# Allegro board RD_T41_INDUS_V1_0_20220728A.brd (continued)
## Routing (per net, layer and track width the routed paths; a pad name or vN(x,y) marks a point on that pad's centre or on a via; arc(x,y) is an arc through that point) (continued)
DVP_D6: length 47.4
  TOP w0.102: U7.H2 56.05,39.12 56.05,42.1 55.72,42.43 55.72,49.41 60.78,54.47 60.78,60.78 57.88,63.68 53.15,63.68 45.42,71.41 J10.18
DVP_D7: length 45.2
  TOP w0.102: J10.19 45.92,71.44 53.18,64.18 57.72,64.18 61.02,60.88 61.02,54.24 55.95,49.17 55.95,42.52 56.26,42.2 56.26,39.27 56.31,39.22 56.31,38.73 U7.H3
DVP_D8: length 43.5
  TOP w0.102: U7.G1 56.47,39.85 56.47,42.31 56.19,42.59 56.19,49.06 61.27,54.15 61.27,61.03 57.64,64.66 53.16,64.66 46.92,70.9 J10.21
DVP_D9: length 46.7
  TOP w0.102: J10.22 47.42,71.02 53.28,65.16 57.52,65.16 61.51,61.17 61.51,54.02 56.45,48.96 56.45,45.76 56.45,42.64 56.68,42.41 56.68,40.08 56.93,39.83 56.93,39.57 56.63,39.26 U7.G2
DVP_D10: length 44.6
  TOP w0.102: J10.23 47.92,71.02 53.26,65.68 57.44,65.68 61.78,61.34 61.78,53.96 56.68,48.86 56.68,45.85 56.68,42.75 56.91,42.52 56.91,40.23 57.16,39.98 57.16,39.47 56.93,39.24 56.93,38.7 U7.G3
DVP_D11: length 46.4
  TOP w0.102: U7.F2 57.39,39.16 57.39,40.09 57.12,40.36 57.12,42.66 56.91,42.88 56.91,48.77 62.04,53.9 62.04,61.46 57.42,66.08 53.24,66.08 48.42,70.9 J10.24
DVP_HSYNC: length 53.5
  TOP w0.102: TP20.1 40.42,77.17 J10.8 40.42,71.03 50.61,60.85 57.01,60.85 60.24,57.61 60.24,54.83 55.19,49.78 55.19,42.31 55.63,41.88 55.63,39.58 55.33,39.27 U7.J2
DVP_MCLK_PA15: length 22.5
  TOP w0.102: J10.28 50.42,70.5 53.34,67.58 TP10.1 54.98,68.31 57.24,68.31 63.63,61.92 R126.2
DVP_PCLK: length 47.8
  TOP w0.102: J10.26 49.42,70.44 52.97,66.89 55.29,66.89 TP19.1 56.52,66.94 57.38,66.94 62.6,61.71 62.6,53.33 57.17,47.9 57.17,43.09 57.34,42.92 57.34,40.48 57.61,40.2 57.61,38.74 U7.F3
DVP_VSYNC: length 53.8
  TOP w0.102: U7.J3 55.64,38.72 55.64,39.2 55.84,39.4 55.84,41.98 55.42,42.4 55.42,49.6 60.53,54.71 60.53,57.68 57.09,61.12 50.98,61.12 40.92,71.18 J10.9 40.92,77.58 TP22.1
EMMC_3V3: length 6.2
  TOP w0.254: U11.E6 66.57,8.07 v1(66.52,8.12) 66.52,8.12 U11.F5 ; U11.K9 64.99,6.57 v1(64.99,6.57) 64.99,6.1 U11.J10
  BOTTOM w0.381: v1(66.52,8.12) 66.52,8.05 C88.1 65.05,6.57 v1(64.99,6.57) 64.59,6.17 C87.1 64.58,5.85 FB1.2
EMMC_D4: length 5.5
  TOP w0.081: 69.2,9.82 68.77,9.82
  TOP w0.102: 69.2,9.82 69.34,9.97 69.34,13.22 68.55,14.01 R74.2 ; 68.77,9.82 U11.B3
EMMC_D5: length 6.4
  TOP w0.081: 69.42,9.32 68.77,9.32
  TOP w0.102: 68.77,9.32 U11.B4 ; 69.42,9.32 70.11,10.01 70.11,13.65 R75.2
EMMC_D6: length 7.3
  TOP w0.081: 68.84,8.82 69.55,8.82
  TOP w0.102: 68.84,8.82 68.78,8.82 U11.B5 ; R76.2 70.92,13.72 70.92,10.07 69.67,8.82 69.55,8.82
EMMC_D7: length 8.2
  TOP w0.081: U11.B6 68.78,8.32 69.63,8.32
  TOP w0.102: R77.2 71.65,13.87 71.65,10.04 69.93,8.32 69.63,8.32
EMMC_DS: length 1.4
  TOP w0.102: U11.H5 65.52,8.89 v1(65.71,9.08)
  BOTTOM w0.102: TP33.1 65.89,8.9 v1(65.71,9.08)
EMMC_MSC0_CLK: length 17.6
  TOP w0.102: R86.2 v1(63.44,17.73) ; v1(64.01,7.76) 63.84,7.76 U11.M6
  BOTTOM w0.102: v1(63.44,17.73) 63.44,17.79 62.68,18.55 60.76,18.55 60.36,18.16 60.36,17.22 65.09,12.49 C91.1 65.09,8.84 v1(64.01,7.76)
EMMC_MSC0_CMD: length 19.9
  TOP w0.102: v1(63.98,8.39) 63.81,8.57 U11.M5 ; R84.2 v1(64.6,17.79)
  BOTTOM w0.102: v1(64.6,17.79) 63.25,19.14 60.46,19.14 59.64,18.33 59.64,16.36 64.25,11.75 64.25,8.66 v1(63.98,8.39) 63.56,8.39 R78.2
EMMC_MSC0_D0: length 16
  TOP w0.102: U11.A3 69.33,9.57 69.75,9.99 v1(69.75,12.23) ; R131.2 v1(62.29,17.79)
  BOTTOM w0.102: v1(62.29,17.79) 67.85,12.23 v1(69.75,12.23) 70.48,12.23 71.51,11.19 R70.2
EMMC_MSC0_D1: length 16.6
  TOP w0.102: U11.A4 69.56,9.07 70.56,10.07 70.56,11.49 v1(70.53,11.52) ; R133.2 v1(61.14,17.79)
  BOTTOM w0.102: v1(61.14,17.79) 67.23,11.69 70.36,11.69 v1(70.53,11.52) 70.57,11.48 R71.2
EMMC_MSC0_D2: length 16.8
  TOP w0.102: v1(71.3,12.89) 71.3,10.07 69.8,8.57 69.8,8.57 U11.A5 ; R135.2 v1(66.9,17.76)
  BOTTOM w0.102: R72.2 73.26,10.92 v1(71.3,12.89) 71.13,13.05 69.55,13.05 66.9,15.7 v1(66.9,17.76)
EMMC_MSC0_D3: length 14.1
  TOP w0.081: 68.77,10.32 68.77,10.73
  TOP w0.102: 68.77,10.73 v1(68.77,12.75) ; U11.B2 68.77,10.32 ; R137.2 v1(65.75,17.79)
  BOTTOM w0.102: R73.2 70.76,12.62 68.9,12.62 v1(68.77,12.75) 65.75,15.77 v1(65.75,17.79)
EMMC_RST_PB21: length 33.3
  TOP w0.102: v1(63.42,21.59) 63.24,21.77 63.24,24.73 59.22,28.75 U7.C17 ; v1(65.03,7.39) 64.87,7.54 64.87,8.22 U11.K5
  BOTTOM w0.102: v1(65.03,7.39) 64.14,7.39 C92.1 63.34,6.59 62.05,6.59 R79.1 60.85,7.79 60.85,9.13 61.24,9.53 61.24,13.47 59,15.72 59,18.47 60.24,19.71 61.23,19.71 63.11,21.59 v1(63.42,21.59)
EMMC_VDDI: length 3.7
  TOP w0.081: 68.27,10.73 68.27,10.32 68.23,10.27 ; 67.77,10.32 67.77,10.73
  TOP w0.102: 68.27,10.73 68.27,10.84 68.05,11.07 v1(67.96,11.07) 67.77,10.88 67.77,10.73 ; 67.77,10.32 U11.C2 68.23,10.27
  BOTTOM w0.203: C93.1 v1(67.96,11.07)
EXCLKI: length 5.9
  TOP w0.102: C66.2 61.46,43.28 Y1.1 60.92,42.74 R41.2 60.4,41.1 59.78,41.1 59.13,40.45 59.13,39.8 U7.C1
EXCLKO: length 8.1
  TOP w0.102: U7.D2 58.88,39.35 58.88,40.62 R41.1 60.23,41.97 60.23,43.97 Y1.3 59.49,45.72 C67.2
GMAC_MDC: length 18.2
  TOP w0.102: R177.2 42.12,27.54 42.12,21.93 41.06,20.87 38.92,20.87 37.6,19.55 U19.22
GMAC_MDIO: length 19
  TOP w0.102: R178.2 41.72,28.03 41.72,22.13 40.72,21.13 39.43,21.13 R189.2 38.97,21.36 37.65,20.05 U19.23
GMAC_NRST_PB28: length 66.1
  TOP w0.102: v1(68.89,17) 68.52,17 67.63,16.11 67.63,13.24 66.22,11.82 43.11,11.82 v1(42.24,12.69) ; v1(40.64,18.89) R207.2 C151.1 38.7,19.05 U19.21 ; v1(67.93,33.49) 67.81,33.37 66.11,33.37 65.76,33.72 61.21,33.72 60.68,33.2 U7.A11
  L3_PWR w0.102: v1(68.89,17) 68.89,32.78 68.59,33.08 68.33,33.08 v1(67.93,33.49)
  BOTTOM w0.102: v1(42.24,12.69) 42.24,14.51 41.9,14.85 41.9,15.37 41.07,16.2 41.07,18.47 v1(40.64,18.89)
GMAC_PHY_CLK: length 20.2
  TOP w0.102: R175.2 46.68,34.08 45.65,34.08 37.56,25.99 35.59,25.99 33.51,23.91 U19.31
GMAC_RXD0: length 30.9
  TOP w0.102: R195.1 33.04,12.71 36.93,12.71 40.59,16.36 41.47,16.36 44.37,19.26 44.37,25.46 47.4,28.49 48.23,28.49 49.8,30.06 49.8,31.57 U7.U13
GMAC_RXD1: length 32.1
  TOP w0.102: R198.1 33.85,13.69 R193.1 v1(34.41,13.14) 34.51,13.04 36.87,13.04 40.48,16.65 41.21,16.65 44.05,19.48 44.05,25.64 47.18,28.77 48.15,28.77 49.54,30.16 49.54,31.74 50.01,32.21 51.09,32.21 U7.R12
  BOTTOM w0.102: v1(34.41,13.14) 33.87,13.67 R192.2
GMAC_RXDV: length 18.8
  TOP w0.102: U7.U9 49.85,34.22 48.65,34.22 48.09,33.67 46.25,33.67 37.7,25.12 36.54,25.12 35.9,24.47 R191.1
GMAC_TXCLK: length 26.6
  TOP w0.102: R190.1 40.28,17.26 41.27,17.26 43.65,19.63 43.65,26 46.69,29.04 48.1,29.04 49.31,30.26 49.31,31.86 49.89,32.44 50.67,32.44 U7.T12
GMAC_TXD0: length 20
  TOP w0.102: R179.2 46.63,29.59 43.18,26.14 43.18,19.78 41.18,17.78 40.12,17.78 38.3,15.95 36.72,15.95 36.51,16.16 U19.16
GMAC_TXD1: length 19
  TOP w0.102: R180.2 42.87,26.51 42.87,19.94 40.98,18.04 39.86,18.04 38.87,17.05 U19.17
GMAC_TXEN: length 19.3
  TOP w0.102: R176.2 42.51,27.04 42.51,19.99 40.85,18.33 38.46,18.33 38.23,18.55 U19.20
HPOUT: length 55.6
  TOP w0.203: U7.T1 39.44,51.04 31.76,51.04 11.61,71.19 C76.2
I2C0_MIPI_DVP_SCK: length 58.2
  TOP w0.102: J11.20 46.37,60.61 TP29.1 46.37,60.89 v1(46.37,62.2) 46.37,63.87 38.62,71.62 38.61,71.62 38.52,71.71 38.52,71.72 J10.3 ; v1(48,61.92) 49.8,60.11 56.99,60.11 59.69,57.42 59.69,55.04 54.63,49.98 54.63,42.16 55.17,41.62 55.17,39.97 55.02,39.82 55.02,38.05 U7.J4
  BOTTOM w0.102: v1(48,61.92) 46.66,61.92 v1(46.37,62.2)
I2C0_MIPI_DVP_SDA: length 56
  TOP w0.102: 46.88,63.86 39.42,71.32 J10.6 ; 46.88,63.86 50.23,60.52 56.98,60.52 59.95,57.54 59.95,54.93 54.9,49.87 54.9,42.25 55.38,41.77 55.38,39.75 U7.J1 ; 46.88,63.86 TP28.1 46.88,57.94 J11.19
I2C1_SCK_PB26: length 79.4
  TOP w0.102: v1(42.8,41.03) 42.41,40.64 35.01,40.64 33.83,41.82 29.89,41.82 29.34,41.27 24.98,41.27 v1(19.34,35.63) ; U21.6 78.69,37.55 78.24,37.1 74.23,37.1 R152.1 73.3,36.17 73.3,35.08 72.08,33.86 67.2,33.86 v1(67.18,33.89) 67.18,34.25 R184.1
  BOTTOM w0.102: U9.7 16.91,35.57 R46.2 17.74,35.63 v1(19.34,35.63) ; v1(42.8,41.03) 42.8,41.47 46.83,45.5 57.47,45.5 57.95,45.02 61.01,45.02 67.26,38.76 67.26,33.97 v1(67.18,33.89)
I2C1_SDA_PB25: length 85.7
  TOP w0.102: v1(66.5,32.29) 66.78,32.01 R182.1 67.75,31.38 72.01,31.38 74.39,33.77 74.39,36.17 R140.1 79.12,36.72 79.96,37.55 U21.5 ; v1(17.3,33.55) 18.42,33.55 25.91,41.04 29.48,41.04 30,41.56 33.76,41.56 34.93,40.39 42.73,40.39 v1(43.36,41.02)
  BOTTOM w0.102: v1(17.3,33.55) R40.2 16.52,35.07 U9.8 ; v1(43.36,41.02) 43.36,41.68 46.95,45.27 57.34,45.27 57.84,44.77 60.89,44.77 66.82,38.85 66.82,32.61 v1(66.5,32.29)
IRLED_EN_N_PB19: length 99.2
  TOP w0.102: v1(62.32,22.27) 62.32,24.65 58.69,28.28 58.69,29.83 U7.D16
  L3_PWR w0.102: v1(34.11,78.68) 34.11,74.23 v1(43.23,65.1)
  BOTTOM w0.102: Q8.1 28.08,79.86 29,78.94 31.11,78.94 R165.1 32.2,78.69 C102.2 v1(34.11,78.68) ; v1(62.32,22.27) 62.32,22.04 60.76,20.48 49.35,20.48 39.08,30.75 39.08,46.44 38.06,47.45 38.06,55.69 43.48,61.1 43.48,63.4 43.23,63.65 v1(43.23,65.1)
KEY1_PB30: length 45.4
  TOP w0.102: SW1.2 100.01,32.85 93.63,32.85 90.24,29.46 87.54,29.46 R89.1 86.61,28.54 72.11,28.54 69.74,30.9 66.91,30.9 65.6,32.21 59.56,32.21 U7.C12
KEY_IOT_N: length 35.1
  TOP w0.102: SW2.1 100.83,66.44 98.45,64.06 D10.2 96.26,64.06 C95.2 96.18,63.99 R90.2 91.83,60.58 83.15,60.58 73.37,50.8 J9.18
LDR0: length 100.4
  TOP w0.102: v1(60.51,68.01) 60.51,68.03 62.52,70.05 62.52,79.95 68.88,86.31 76.53,86.31 76.98,86.76 76.98,87.92 C125.1 ; R92.1 C125.1 ; C125.1 77.44,89.3 R113.1 ; v1(47.29,25.85) 50.12,28.68 51.32,28.68 51.75,29.1 51.75,30.27 U7.P15
  BOTTOM w0.152: v1(60.51,68.01) 57.14,64.65 53.99,64.65 46.91,57.56 42.39,57.56 39.41,54.59 39.41,48.29 40.44,47.26 40.44,31.75 46.34,25.85 v1(47.29,25.85)
LED_G: length 5.4
  TOP w0.102: v1(69.89,35.39) 69.89,36.32 70.6,37.03 ; v1(69.89,32.67) 69.98,32.58 R181.1
  BOTTOM w0.102: v1(69.89,35.39) v1(69.89,32.67)
LED_R_IOT: length 30.5
  TOP w0.102: R95.1 73.41,41.25 73.41,43.3 80.6,50.49 v1(88.12,50.49) ; v1(88.31,56.85) 88.42,56.97 R225.1
  BOTTOM w0.102: v1(88.31,56.85) 88.04,56.59 88.04,50.57 v1(88.12,50.49)
MCU_PWR: length 100.3
  TOP w0.254: v1(41.64,41.01) 41.62,41 35.1,41 33.89,42.21 24.17,42.21 v1(18.92,36.96) ; v1(86.29,45.93) 81.83,45.93 79.89,43.99 76.54,43.99 v1(76.17,44.36) ; R8.2 v1(89.89,59) ; R90.1 v1(95.24,59.17)
  BOTTOM w0.254: v1(76.17,44.36) 64.25,44.36 62.04,46.57 46.02,46.57 41.64,42.18 v1(41.64,41.01) ; R47.1 v1(18.92,36.96) ; R54.1 88.01,47.83 89.52,47.83 90.85,49.16 90.85,58.04 v1(89.89,59) 95.07,59 v1(95.24,59.17)
  vias: v1(87.25,45.91)
MICBIAS: length 55.7
  TOP w0.254: U7.P3 v1(51.75,38.72)
  TOP w0.305: v1(51.75,41.68) 51.75,42.83 40.96,53.62 38.84,53.62 22.07,70.39 R83.2
  BOTTOM w0.381: v1(51.75,41.68) 51.39,41.32 51.39,40.62 51.75,40.26 v1(51.75,38.72) ; C142.1 51.96,38.93 v1(51.75,38.72) ; v1(51.75,38.72) 51.81,38.66 C141.1
MICNL: length 58.1
  TOP w0.152: C65.2 49.07,43.17 39.89,52.35 38.19,52.35 20.37,70.18 20.37,83.02 R69.1 20.36,83.65 20.36,83.93 C78.1 20.33,84.58 20.33,84.98 D15.2 20.32,85.64 20.32,86.31 19.89,86.74 J7.1
MICPL: length 58
  TOP w0.152: 49.7,43.55 49.19,43.55 40.03,52.71 38.34,52.71 20.72,70.33 20.72,83.02 R80.2 20.72,83.65 20.72,83.93 C78.2 20.69,84.65 20.69,84.91 D9.2 20.68,85.72 20.68,86.3 21.14,86.76 J7.2
MIPI_DVP_IRCUTN_PB18: length 89.4
  TOP w0.102: J11.25 v1(43.87,63.08) ; U7.E17 57.93,27.55 61.04,24.43 61.04,21.59 v1(61.07,21.56) ; J10.31 v1(51.92,71.17)
  BOTTOM w0.102: v1(61.07,21.56) 60.24,20.73 49.46,20.73 39.36,30.83 39.36,46.54 38.32,47.58 38.32,55.54 43.87,61.09 v1(43.87,63.08) 44.06,63.27 44.06,65.41 48.88,70.23 51.3,70.23 51.92,70.85 v1(51.92,71.17)
MIPI_DVP_IRCUTP_PB17: length 96.1
  TOP w0.102: U7.E16 57.93,29.77 58.23,29.47 58.23,27.77 61.45,24.55 v1(61.45,22.3) ; J10.32 v1(52.42,70.67) ; J11.24 44.37,63.83 v1(44.49,63.95)
  BOTTOM w0.102: v1(61.45,22.3) 61.24,22.3 59.94,20.99 49.6,20.99 39.59,31.01 39.59,46.68 38.56,47.71 38.56,55.41 44.19,61.04 44.19,62.73 44.49,63.03 v1(44.49,63.95) 44.49,65.28 49.07,69.86 51.7,69.86 52.42,70.58 v1(52.42,70.67)
MIPI_DVP_MCLK: length 18.9
  TOP w0.102: R126.1 63.63,60.3 R125.1 64.36,58.73 64.36,56.41 63.19,55.24 63.19,52.8 57.63,47.25 TP27.1 57.63,45.33 R38.1
MIPI_DVP_PWDN_PA19: length 24.3
  TOP w0.102: v1(43.59,63.98) 43.37,63.76 43.37,60.75 TP31.1 43.37,60.37 J11.26 ; v1(48.92,71.24) J10.25 ; R143.1 52.47,69.26 v1(51.01,70.72)
  BOTTOM w0.102: v1(51.01,70.72) 49.44,70.72 v1(48.92,71.24) 48.92,70.79 43.59,65.45 v1(43.59,63.98)
MIPI_DVP_RESET: length 62.2
  TOP w0.102: J11.18 47.37,60.55 TP30.1 47.37,60.95 v1(47.37,62.46) ; J10.33 v1(52.92,70.44) 53.66,69.7 57.65,69.7 65.38,61.96 65.38,55.76 64.19,54.58 64.19,51.76 58.53,46.09 58.53,39.52 58.26,39.25 58.26,38.73 U7.E3
  BOTTOM w0.102: v1(52.92,70.44) 52.92,69.56 47.37,64.02 v1(47.37,62.46)
MIPI_MCLK_PA15: length 26.8
  TOP w0.102: R125.2 63.62,58.41 TP32.1 63.62,56.7 v1(63.34,56.41) ; J11.22 v1(45.37,56.35)
  BOTTOM w0.102: v1(63.34,56.41) 63.34,58.69 60.57,61.46 52.08,61.46 47.19,56.57 45.59,56.57 v1(45.37,56.35)
MIPI_RX_2LANE_CLKN0: length 9.6
  TOP w0.104: v1(55.12,56.31) 55.37,56.06 J11.2 ; v1(50.47,53.59) 50.63,53.44 50.63,53.19 R110.2
  BOTTOM w0.104: v1(55.12,56.31) 55.29,56.31 55.45,56.16 55.45,55.19 54.24,53.99 53.67,53.99 53.5,54.16 53.3,54.16 53.13,53.99 52.85,53.99 52.66,54.17 52.47,54.17 52.28,53.99 50.86,53.99 v1(50.47,53.59)
MIPI_RX_2LANE_CLKP0: length 9.6
  TOP w0.104: J11.3 54.87,57.1 v1(55.12,56.85) ; v1(51.08,53.59) 50.89,53.4 50.89,53.19 R108.2
  BOTTOM w0.104: v1(55.12,56.85) 55.7,56.26 55.7,55.09 54.35,53.73 51.22,53.73 v1(51.08,53.59)
MIPI_RX_2LANE_DN0: length 10.4
  TOP w0.104: J11.5 53.87,54.75 53.8,54.68 53.8,54.53 54.04,54.3 56,54.3 56.41,53.88 56.41,53.04 55.68,52.31 54.81,52.31 54.25,52.87 53.92,52.87 R102.2
MIPI_RX_2LANE_DN1: length 8.6
  TOP w0.104: R106.2 48.28,53.21 48.28,53.45 v1(48.13,53.61) ; v1(52.12,56.31) 52.37,56.06 J11.8
  BOTTOM w0.104: v1(52.12,56.31) 52.31,56.13 52.31,55.64 51.8,55.14 49.73,55.14 49.52,54.93 49.35,54.93 49.24,55.04 49.07,55.04 48.95,54.92 48.95,54.74 49.06,54.64 49.06,54.46 48.2,53.61 v1(48.13,53.61)
MIPI_RX_2LANE_DP0: length 10.1
  TOP w0.104: R100.2 53,53.12 54.36,53.12 54.92,52.57 55.58,52.57 56.16,53.15 56.16,53.78 55.89,54.04 55.49,54.04 55.37,53.92 55.37,53.26 55.24,53.14 55.07,53.14 54.95,53.26 54.95,53.92 54.83,54.04 53.93,54.04 53.54,54.43 53.54,54.67 53.37,54.84 J11.6
MIPI_RX_2LANE_DP1: length 8.5
  TOP w0.104: R104.2 48.54,53.2 48.54,53.42 v1(48.74,53.61) ; v1(52.12,56.85) 51.87,57.1 J11.9
  BOTTOM w0.104: v1(48.74,53.61) 48.74,53.78 49.84,54.88 51.91,54.88 52.56,55.53 52.56,56.4 v1(52.12,56.85)
MSC0_CLK: length 16.5
  TOP w0.102: R39.2 55.86,25.51 55.86,22.5 59.1,19.26 63.06,19.26 64.01,18.31 64.01,16.68 R86.1 R85.1
MSC0_CMD: length 20.4
  TOP w0.102: R82.1 R84.1 65.15,16.67 65.15,18.85 64.14,19.85 59.63,19.85 56.71,22.77 56.71,29.22 U7.G17
MSC0_D0: length 20.5
  TOP w0.102: U7.H16 55.98,27.47 55.09,26.58 55.09,22.19 58.63,18.65 62.09,18.65 62.89,17.85 62.89,16.72 R131.1 R87.1
MSC0_D1: length 20.4
  TOP w0.102: R132.1 R133.1 61.72,16.7 61.72,17.87 61.35,18.24 58.67,18.24 54.83,22.09 54.83,26.71 55.63,27.51 55.63,30.3 U7.J15
MSC0_D2: length 22.9
  TOP w0.102: U7.G15 56.94,30.29 56.94,29.85 57.17,29.62 57.17,23.06 59.82,20.41 64.78,20.41 67.49,17.7 67.49,16.7 R135.1 R134.1
MSC0_D3: length 21.6
  TOP w0.102: R136.1 R137.1 66.35,16.71 66.35,18.21 64.43,20.13 59.76,20.13 56.94,22.95 56.94,29.47 56.63,29.78 U7.G16
NTC: length 5.2
  BOTTOM w0.102: TP3.1 17.91,40.01 R11.2 R9.1 17.53,42.84 U1.7
OSC32_XI: length 7.3
  TOP w0.102: Y3.2 52.25,24.89 51.31,25.84 C71.2 51.31,26.92 R52.2 51.46,27.7 51.66,27.89 52.72,27.89 53.38,28.55 U7.M16
OSC32_XO: length 8.3
  TOP w0.102: U7.M15 53.05,30.28 53.05,28.69 52.56,28.19 51.54,28.19 R52.1 50.57,26.92 C72.2 50.57,25.33 Y3.1
OU_PWR_EN_PC18: length 114.6
  TOP w0.102: v1(66.18,60.91) v1(66.18,82.54) ; U7.B5 60.07,37.1 60.39,36.78 60.91,36.78 61.68,37.55 63.4,37.55 v1(74.99,49.14)
  BOTTOM w0.102: v1(74.99,49.14) 74.99,49.27 74.74,49.52 71.53,49.52 68.92,52.13 68.92,58.17 v1(66.18,60.91) ; v1(66.18,82.54) 66.18,82.77 65.01,83.95 40.4,83.95 27.93,71.48 21.2,71.48 19.97,70.25 R233.1 18.44,69.83 D12.2
PHY_LED0: length 22.9
  TOP w0.102: v1(29.93,25.23) 22.01,25.23 R211.2 ; v1(38.39,23.38) R203.1 R202.2 38.45,21.98 38.45,21.56 37.44,20.55 U19.24
  BOTTOM w0.102: v1(29.93,25.23) 35.68,25.23 37.53,23.38 v1(38.39,23.38)
PHY_LED1: length 41.1
  TOP w0.102: R217.2 17.66,5.68 21.37,5.68 23.19,3.86 30.43,3.86 37.68,11.11 v1(37.68,12.2) ; U19.25 36.51,22.7 R206.1 R205.2 v1(37.68,22.52)
  BOTTOM w0.102: v1(37.68,22.52) v1(37.68,12.2)
PIR_3V3: length 51.4
  TOP w0.508: 84.24,70.72 84.24,74.18 ; 84.24,70.72 84.24,70.22 ; 84.24,70.72 84.47,70.49 84.5,70.49 ; 84.24,74.18 84.52,74.46 ; 84.24,74.18 84.24,74.73 ; 84.24,70.22 84.5,70.49 ; 84.24,70.22 84.24,68.62 82.28,66.66 v1(74.78,66.66) ; v1(92.61,72.31) 92.57,72.35 92.57,72.63 90.74,74.46 v1(89.26,74.46) 84.52,74.46 ; 84.5,70.49 v1(86.91,70.49) ; 84.52,74.46 84.5,74.46 84.24,74.73 ; U25.3 92.85,81.63 85.15,81.63 v1(84.58,81.05) 84.24,80.71 v1(84.24,80.64) 84.24,74.73
  BOTTOM w0.254: R265.2 v1(92.61,72.31) ; v1(89.26,74.46) C127.1 88.67,74.46 R227.2 ; D18.1 97.56,75.38 ; U24.4 v1(86.91,70.49) ; R258.2 v1(74.78,66.66)
PIR_H_IOT: length 29.3
  TOP w0.102: v1(92.92,62.61) 92.92,66.27 v1(86.76,72.44)
  BOTTOM w0.102: Q6.1 v1(92.92,62.61) 97.07,58.46 97.07,52.75 96.23,51.91 95.11,51.91 J14.11 ; U24.1 v1(86.76,72.44)
PIR_IOT: length 40.9
  TOP w0.102: R230.1 89.58,48.59 v1(88.97,49.21)
  BOTTOM w0.102: v1(88.97,49.21) 88.15,49.21 87.43,49.94 87.43,64.28 R257.2 88.86,66.96 90.01,68.1 90.01,71.14 91.52,72.65 91.52,79.37 U25.4
PIR_L_IOT: length 28
  TOP w0.102: v1(86.66,68.22) 88.85,68.22 v1(91.03,66.04)
  BOTTOM w0.102: v1(91.03,66.04) Q7.1 93.22,64.77 93.22,63.35 97.87,58.71 97.87,52.1 96.45,50.68 95.16,50.68 J14.13 ; v1(86.66,68.22) 86.35,68.54 U24.7
PIR_PWR_EN_IOT: length 32.5
  TOP w0.102: v1(92.44,71.39) 96.08,71.39 v1(97.77,73.07) ; R220.1 v1(89.89,53.41)
  BOTTOM w0.102: v1(89.89,53.41) 89.17,54.14 89.17,66.47 90.62,67.93 90.62,69.57 v1(92.44,71.39)
  BOTTOM w0.203: U15.3 95.18,72.55 95.7,73.07 v1(97.77,73.07) C126.1 98.61,74.41 D18.2
PLL_AVDD18: length 5.4
  TOP w0.254: U7.D3 v1(58.9,38.72)
  BOTTOM w0.381: v1(58.9,38.72) 58.9,40.43 59.31,40.85 59.78,40.85 C60.1 C59.1 60.03,41.48 FB3.1
POR_CTRL: length 11.5
  TOP w0.102: R122.2 51.89,22.26 53.43,22.26 54,22.84 54,27.17 v1(54.17,27.33) 54.77,27.93 54.77,29.86 U7.K16
  BOTTOM w0.102: v1(54.17,27.33) 54.11,27.27 R121.2
PWR_ON_PC16: length 45.9
  TOP w0.102: J14.2 93.71,59.73 82.83,59.73 71.75,48.65 70.62,48.65 66.95,44.97 66.95,43.28 62.32,38.66 60.78,38.66 U7.A3
PWRON: length 12.8
  TOP w0.102: TP12.1 50.71,22.63 53.35,22.63 53.72,23.01 53.72,27.43 54.52,28.23 54.52,29.52 54.37,29.67 54.37,30.3 U7.K15
RMII_MDCK: length 4.4
  TOP w0.102: U7.R10 51.08,33.5 48.73,33.5 48.33,33.1 48.33,32.71 R177.1
RMII_MDIO: length 3.2
  TOP w0.102: R178.1 48.59,33.85 U7.T10
RMII_PHY_CLK: length 3.3
  TOP w0.102: R175.1 48.19,34.55 49.47,34.55 49.74,34.82 50.27,34.82 50.58,34.5 U7.T9
RMII_TX0: length 5.7
  TOP w0.102: U7.R11 51.1,32.87 50.61,32.87 50.41,32.67 49.8,32.67 48.56,31.42 48.56,30.78 48.31,30.53 48.31,30.02 R179.1
RMII_TX1: length 4.4
  TOP w0.102: U7.T11 50.56,33.2 50.26,32.9 49.69,32.9 48.3,31.5 48.3,30.89 R180.1
RMII_TXEN: length 3
  TOP w0.102: R176.1 47.88,31.44 49.65,33.2 U7.U11
RST_OUT: length 9.9
  TOP w0.102: TP14.1 53.06,21.4 54.27,22.61 54.27,26.84 55.01,27.58 55.01,29.63 U7.J16
RTC_0V8: length 28.9
  TOP w0.254: U13.5 73.84,20.47 C99.1 72.67,21.66 TP34.1 64.31,22.57 v1(64.22,22.65) ; U7.L15 v1(53.7,30.28)
  BOTTOM w0.381: 53.35,26.94 53.01,27.27 53.01,28.76 53.61,29.36 C143.1 53.7,29.56 v1(53.7,30.28)
  BOTTOM w0.508: 53.35,26.94 53.38,26.9 53.38,25.49 55.78,23.09 58.8,23.09 59.55,23.83 63.04,23.83 v1(64.22,22.65)
RTC_1V8: length 39.4
  TOP w0.254: U13.1 75.33,18.34 R142.1
  TOP w0.381: U7.L17 54.03,28.97 v1(54.15,28.84)
  TOP w0.457: C98.1 77.38,15.76 R97.2
  TOP w0.508: v1(71.41,17.73) 72.75,16.4 TP36.1 76.74,16.4 C98.1 76.75,17.56 U13.1
  BOTTOM w0.254: R121.1 54.77,25.8 54.77,25.8
  BOTTOM w0.305: C169.1 54.56,28.43 v1(54.15,28.84)
  BOTTOM w0.508: C169.1 54.77,25.12 56.14,23.75 58.56,23.75 59.33,24.52 63.55,24.52 70.34,17.73 v1(71.41,17.73) C94.1 71.46,16.7 U12.5
RTC_IRQ_N_PB29: length 21.8
  TOP w0.102: U7.B12 59.98,32.44 65.74,32.44 67.03,31.15 72.26,31.15 R153.1 75.39,34.28 77.87,34.28 78.69,33.46 U21.3
RX+: length 17.4
  TOP w0.254: J13.3 7.46,17.39 8.52,18.45 8.52,19.07 8.21,19.39 8.21,20.19 8.81,20.79 11.2,20.79 12.08,19.91 12.08,19.09 15.82,15.34 16.63,15.34 17.66,16.38 U20.14
RX-: length 17.5
  TOP w0.254: U20.16 17.59,13.84 16.63,14.8 15.6,14.8 14.63,15.77 14.21,15.77 13.47,15.03 13.05,15.03 12.75,15.33 12.75,15.75 13.49,16.49 13.49,16.91 13.2,17.21 12.78,17.21 12.03,16.47 11.61,16.47 11.31,16.77 11.31,17.19 12.06,17.93 12.06,18.35 11.54,18.86 11.54,19.69 10.98,20.25 9.71,20.25 J13.6
RX_N1: length 7.8
  TOP w0.104: U19.6 31.81,18.05 31.69,18.17 30.99,18.17 30.04,17.22 30.04,15.51 29.43,14.9 28.92,14.9 27.86,13.84 U20.1
RX_P1: length 7.8
  TOP w0.104: U19.5 31.81,18.55 31.69,18.43 30.88,18.43 29.78,17.33 29.78,15.62 29.32,15.16 29.06,15.16 27.84,16.38 U20.3
RXDV: length 2.5
  TOP w0.102: v1(31.67,16.65) 32.07,17.05 U19.8
  BOTTOM w0.102: v1(31.67,16.65) 31.67,16.06 R196.2 30.89,15.92 R197.1
SD0_CD_N_PB27: length 62.1
  TOP w0.102: J6.9 v1(41.87,13.51) 41.87,12.52 42.81,11.58 66.32,11.58 67.89,13.15 67.89,16 68.5,16.61 69.08,16.61 v1(69.49,17.02) ; v1(68.47,33.47) 68.13,33.13 66.01,33.13 65.66,33.48 61.29,33.48 60.7,32.9 60.4,32.9 60.1,33.2 U7.B11
  L3_PWR w0.102: v1(69.49,17.02) 69.13,17.38 69.13,32.92 68.58,33.47 v1(68.47,33.47)
  BOTTOM w0.102: v1(41.87,13.51) 41.87,14.42 R88.1
SD0_MSC0_CLK: length 22
  TOP w0.102: R85.2 63.44,13.74 63.06,13.35 59.88,13.35 55.22,18.01 47.76,18.01 46.28,16.53 J6.5
SD0_MSC0_CMD: length 21.4
  TOP w0.102: J6.3 v1(48.47,16.32) 49.42,17.26 54.9,17.26 59.3,12.86 63.87,12.86 64.6,13.58 R82.2
  BOTTOM w0.102: v1(48.47,16.32) 48.48,16.31 R61.2
SD0_MSC0_D0: length 23.4
  TOP w0.102: J6.7 v1(44.07,16.32) 46.39,18.63 55.71,18.63 60.46,13.88 61.87,13.88 R87.2
  BOTTOM w0.102: v1(44.07,16.32) 44.06,16.3 R62.2
SD0_MSC0_D1: length 23.3
  TOP w0.102: J6.8 v1(42.97,16.32) 45.69,19.03 55.83,19.03 60.56,14.31 R132.2
  BOTTOM w0.102: R63.2 42.97,16.31 v1(42.97,16.32)
SD0_MSC0_D2: length 21.3
  TOP w0.102: R134.2 66.9,13.58 65.63,12.3 58.88,12.3 54.69,16.49 50.85,16.49 v1(50.67,16.32) J6.1
  BOTTOM w0.102: v1(50.67,16.32) 50.66,16.3 R64.2
SD0_MSC0_D3: length 21.4
  TOP w0.102: J6.2 v1(49.57,16.32) 50.1,16.84 54.83,16.84 59.11,12.57 64.79,12.57 65.75,13.53 R136.2
  BOTTOM w0.102: v1(49.57,16.32) 49.57,16.31 R65.2
SD_PWR_EN_N_PB20: length 39.1
  TOP w0.102: v1(62.36,21.56) 61.94,21.98 61.94,24.58 58.46,28.06 58.46,29.62 58.23,29.85 58.23,30.29 U7.E15
  BOTTOM w0.102: v1(62.36,21.56) 60.99,20.2 58.77,20.2 56.72,18.15 56.72,11.79 54.79,9.86 49.37,9.86 Q3.1 46.42,10.53 R66.2 44.83,10.54 C82.2
SENS1: length 15.6
  BOTTOM w0.305: U25.2 93.65,76.36 C204.1 R267.2 R265.1 93.65,69.04 92.55,67.94 Q7.2 91.57,67.94 90.31,66.68 90.31,65.34 91.15,64.51 Q6.2
SFC1_CS_N: length 23.5
  TOP w0.102: v1(36.82,34.93) 36.82,35.02 37.81,36.01 48.52,36.01 48.85,36.33 50.43,36.33 50.64,36.12 51.11,36.12 U7.R7
  BOTTOM w0.102: U18.1 33.64,36.56 R123.1 32.26,35.06 36.68,35.06 v1(36.82,34.93)
SFC1_SCLK: length 17.9
  TOP w0.102: v1(36.61,33.13) 39.37,33.13 41.34,35.09 49.3,35.09 49.45,35.24 50.68,35.24 U7.T8
  BOTTOM w0.102: U18.6 36.18,32.7 v1(36.61,33.13)
SFC1_SIO0: length 18.1
  TOP w0.102: U7.R8 51.09,35.49 49.38,35.49 49.22,35.32 40.39,35.32 38.84,33.78 v1(37.45,33.78)
  BOTTOM w0.102: U18.5 v1(37.45,33.78)
SFC1_SIO1: length 18.4
  TOP w0.102: v1(37.61,35.24) 38.14,35.78 48.95,35.78 49.27,36.1 50.3,36.1 50.6,35.8 U7.T7
  BOTTOM w0.102: v1(37.61,35.24) 37.22,35.63 35.46,35.63 34.91,36.18 U18.2
SFC1_SIO2: length 15.6
  TOP w0.102: v1(38.38,35.41) 38.52,35.55 49.09,35.55 49.34,35.8 U7.U7
  BOTTOM w0.102: U18.3 36.18,37.05 36.79,36.44 37.35,36.44 v1(38.38,35.41)
SFC1_SIO3: length 19.4
  TOP w0.102: v1(35.33,32.37) 39.85,32.37 42.3,34.82 49.39,34.82 49.6,35.03 50.43,35.03 50.63,34.83 51.1,34.83 U7.R9
  BOTTOM w0.102: v1(35.33,32.37) 34.91,31.95 U18.7
SFC_CS_N: length 20.1
  TOP w0.102: U8.1 33.58,37.84 33.58,39.02 33.34,39.27 R44.1 33.79,39.64 35.46,37.97 50.56,37.97 U7.T4
SFC_SCLK: length 19.3
  TOP w0.102: U8.6 31.03,32.05 32.4,33.42 33.69,33.42 36.8,36.54 46.68,36.54 R43.1
SFC_SIO0: length 24.4
  TOP w0.102: U7.U5 49.94,37.28 36.61,37.28 33.5,34.18 31.5,34.18 29.76,32.45 U8.5
SFC_SIO1: length 22.1
  TOP w0.102: U7.R5 51.11,37.42 50.59,37.42 50.26,37.74 36.1,37.74 33.97,35.61 33.06,35.61 32.3,36.36 U8.2
SFC_SIO2: length 23.4
  TOP w0.102: U8.3 31.03,35.62 31.67,34.98 33.82,34.98 36.35,37.51 50.16,37.51 50.57,37.1 U7.T5
SFC_SIO3: length 21.8
  TOP w0.102: U7.T6 50.67,36.56 48.51,36.56 48.2,36.24 37.62,36.24 33.91,32.54 33.05,32.54 32.3,31.79 U8.7
SLCD_BLEN: length 41.7
  TOP w0.102: v1(89.32,35.76) 89.02,35.76 83.19,41.59 77,41.59 R183.1
  BOTTOM w0.102: R212.1 98.79,26.56 U23.16 ; R212.1 98.29,26.21 U23.15 ; R212.1 97.54,27.8 95.75,27.8 89.32,34.24 v1(89.32,35.76)
SLCD_BT656_D0: length 36.1
  TOP w0.102: R130.1 90.54,19.85 R144.1 90.05,20.33 82.78,20.33 82.36,20.75 82.36,22.27 78.12,26.51 65.28,26.51 61.19,30.6 U7.A15
SLCD_BT656_D1: length 37.2
  TOP w0.102: R145.1 90.54,18.71 R146.1 90.05,19.19 87.62,19.19 86.78,20.03 82.61,20.03 82.14,20.51 82.14,22.07 78.73,25.48 65.83,25.48 61.03,30.28 60.39,30.28 60.07,30.6 U7.B15
SLCD_BT656_D2: length 37.7
  TOP w0.102: U7.A16 60.9,29.95 65.67,25.19 78.53,25.19 81.84,21.88 81.84,18.84 82.63,18.05 90.05,18.05 R150.1 90.54,17.57 R149.1
SLCD_BT656_D3: length 40
  TOP w0.102: R154.1 90.54,16.42 R155.1 90,16.96 87.84,16.96 87.08,17.72 82.42,17.72 81.45,18.68 81.45,21.88 78.39,24.94 65.43,24.94 60.75,29.62 60.39,29.62 60.19,29.82 60.19,30.15 60.07,30.27 59.56,30.27 U7.C15
SLCD_BT656_D4: length 39.7
  TOP w0.102: U7.A17 60.53,29.3 65.69,24.14 78.84,24.14 81.13,21.84 81.13,16.91 82.52,15.52 88.14,15.52 88.45,15.84 89.98,15.84 R158.1 90.54,15.28 R156.1
SLCD_BT656_D5: length 41.1
  TOP w0.102: U7.B16 59.88,29.78 60.19,29.47 60.19,29.19 65.48,23.9 78.51,23.9 80.84,21.57 80.84,16.64 82.28,15.2 87.59,15.2 88.07,14.72 89.95,14.72 R161.1 90.54,14.14 R160.1
SLCD_BT656_D6: length 42.5
  TOP w0.102: R162.1 90.54,12.99 R163.1 89.92,13.6 88.57,13.6 87.78,12.82 83.04,12.82 80.5,15.36 80.5,21.36 78.23,23.63 65.21,23.63 59.88,28.97 U7.B17
SLCD_BT656_D7: length 43.5
  TOP w0.102: R164.1 90.54,11.85 R166.1 89.98,12.4 82.98,12.4 80.21,15.17 80.21,21.24 78.05,23.4 65.12,23.4 59.56,28.96 59.56,29.62 U7.C16
SLCD_CS: length 34.6
  TOP w0.102: U7.B13 60.07,31.9 60.37,31.6 62.02,31.6 66.16,27.46 78.97,27.46 80.84,25.58 86.99,25.58 88.28,24.3 R171.1
SLCD_CS_PD10: length 4.4
  TOP w0.102: R171.2 93.65,25.63 J15.7
SLCD_D0_PD00: length 4.8
  TOP w0.102: R130.2 94.54,17.63 J15.23
SLCD_D1_PD01: length 4.5
  TOP w0.102: R145.2 93.9,17.13 J15.24
SLCD_D2_PD02: length 4.3
  TOP w0.102: J15.25 93.33,16.63 92.39,17.57 R149.2
SLCD_D3_PD03: length 4
  TOP w0.102: R154.2 92.62,16.13 J15.26
SLCD_D4_PD04: length 4
  TOP w0.102: J15.27 92.66,15.63 R156.2
SLCD_D5_PD05: length 4.3
  TOP w0.102: J15.28 93.31,15.13 R160.2
SLCD_D6_PD06: length 4.6
  TOP w0.102: J15.29 93.95,14.63 R162.2
SLCD_D7_PD07: length 4.8
  TOP w0.102: J15.30 94.59,14.13 R164.2
SLCD_DC: length 35.6
  TOP w0.102: R172.1 88.71,23.41 86.8,25.32 80.67,25.32 78.76,27.22 65.96,27.22 61.82,31.37 60.24,31.37 60.01,31.6 59.53,31.6 U7.C13
SLCD_DC_PD11: length 4.6
  TOP w0.102: J15.8 94.04,25.13 R172.2
SLCD_IOVDD: length 7.3
  TOP w0.292: 94.89,13.13 J15.32
  TOP w0.381: R147.2 91.99,10.1 C105.1 C106.1 93.79,10.68 93.79,12.03 94.89,13.13
SLCD_LEDA: length 4.6
  TOP w0.279: J15.16 v1(94.78,21.13)
  BOTTOM w0.254: 97.05,21.9 97.29,22.14 U23.8
  BOTTOM w0.381: 97.05,21.9 C185.2 96.27,21.13 v1(94.78,21.13)
SLCD_LEDK: length 8
  TOP w0.279: J15.18 v1(97.63,20.13) ; J15.20 v1(97.62,19.13) ; J15.19 97.56,19.63 ; J15.17 97.69,20.63
  BOTTOM w0.229: U23.4 100.25,23.13
  BOTTOM w0.254: U23.6 98.29,21.72 ; 98.79,21.57 U23.5
SLCD_RDY: length 36
  TOP w0.102: R174.1 87.49,21.63 86.43,22.68 82.39,22.68 78.33,26.74 65.53,26.74 61.36,30.91 59.57,30.91 U7.C14
SLCD_RDY_PD12: length 5.8
  TOP w0.102: R157.1 R174.2 94.81,24.13 J15.10
SLCD_RST_PD09: length 18.7
  TOP w0.102: v1(92.98,25.64) 92.52,25.19 R170.2 ; v1(93.02,12) 94.65,13.63 J15.31
  BOTTOM w0.102: v1(92.98,25.64) 92.51,25.17 92.51,12.51 v1(93.02,12)
SLCD_TE: length 33.5
  TOP w0.102: R170.1 89.2,25.19 86.66,27.72 66.35,27.72 62.18,31.9 U7.A13
SLCD_VCI: length 7.7
  TOP w0.292: J15.33 95.14,12.63
  TOP w0.381: 95.14,12.63 94.36,11.85 94.36,10.27 93.26,9.16 C179.1 93.07,9.16 C180.1 91.35,9.16 R148.2
SLCD_WR_BT656_PCLK: length 35
  TOP w0.102: R168.1 91.27,22.52 R169.1 90.02,23.03 82.52,23.03 78.56,26.98 65.75,26.98 61.59,31.14 59.99,31.14 U7.B14
SLCD_WR_PD08: length 4.8
  TOP w0.102: J15.9 94.42,24.63 R168.2
SOC_0V8: length 10.2
  TOP w0.203: U7.N9 v1(52.4,34.83) U7.N8 ; U7.N10 v1(52.4,33.53) ; U7.N6 v1(52.4,36.13) U7.N7
  TOP w0.254: U7.J13 v1(55,32.22) 54.68,31.9 U7.K13 ; U7.L5 v1(54.35,37.43) U7.K5 ; U7.H7 v1(56.3,36.13) U7.H6 ; U7.H12 v1(56.3,32.22) U7.H13 ; U7.M6 v1(53.05,36.78) U7.M5 ; U7.H10 v1(56.3,33.53) U7.H11 ; U7.J5 v1(55.65,37.43) U7.H5 ; U7.H9 v1(56.3,34.83) U7.H8
  BOTTOM w0.381: FB4.1 48.97,35.44
  vias: v1(55.67,31.55) v1(56.2,31.15) v1(57.78,25.58) v1(57.78,24.97) v1(57.79,24.38) v1(58.33,25.59) v1(58.36,24.96) v1(58.36,24.36)
SOC_1V8: length 57.9
  TOP w0.203: U7.N11 v1(52.4,32.87)
  TOP w0.254: U7.K2 v1(54.35,38.72)
  BOTTOM w0.381: 55.41,43.86 55.74,44.19 ; 55.41,43.86 55.41,44.19 55.4,44.19 ; 55.41,43.86 55.41,43.85 ; 54.21,43.78 53.8,44.19 ; 54.21,43.78 54.21,43.81 ; 54.21,43.78 C174.1 C175.1 54.21,39.72 54.35,39.58 v1(54.35,38.72) ; 54.2,44.19 54.21,44.18 54.21,43.81 ; R185.1 64.65,38.41 FB2.2 ; FB7.1 49.89,30.41 49.89,31.88 C176.1 C177.1 51.61,32.48 52.01,32.87 v1(52.4,32.87) ; 54.21,43.81 54.6,44.19 ; 55.41,43.85 FB10.2 ; 55.41,43.85 55.06,44.19
  BOTTOM w0.508: R185.1 63.84,40.25 61.75,42.34 FB3.2 61.13,42.52 60.61,43.04 57.91,43.04 56.76,44.19 51.87,44.19 ; FB7.1 48.39,29.34 43.81,33.92 43.81,36.78 FB5.1 45.07,38.18 44.57,38.69 44.57,40.78 45.47,41.68 v1(45.51,41.68) 45.51,41.92 47.78,44.19 51.21,44.19
  vias: v1(34.91,42.9) v1(35.15,42.48) v1(44.93,41.71)
SOC_3V3: length 134.3
  TOP w0.203: U7.P9 v1(51.75,34.18)
  TOP w0.254: v1(80.04,9.03) 80.34,9.34 R45.2 ; v1(55.04,30.96) U7.J14 ; v1(20.74,35.19) 26.2,40.65 29.68,40.65 30.22,41.2 33.67,41.2 35.15,39.72 v1(37.9,39.72)
  TOP w0.305: R42.2 v1(77.39,9.51)
  TOP w0.381: v1(77.39,9.51) 75.96,8.08 75.96,6.96 76.38,6.54 J4.1 ; v1(64.06,37.65) 64.12,37.65 v1(65.27,38.8)
  TOP w0.508: v1(44.6,34.09) 44.6,34.06 v1(43.67,33.14)
  BOTTOM w0.254: v1(20.74,35.19) R46.1 R40.1 ; v1(77.39,9.51) 77.86,9.03 v1(80.04,9.03)
  BOTTOM w0.381: v1(51.75,34.18) 51.75,34.06 51.73,34.03 51.73,33.49 51.42,33.18 50.06,33.18 49.37,32.49 C171.1 ; R138.1 63.84,37.87 v1(64.06,37.65) ; v1(45.17,40.5) 45.17,39.12 FB6.1 ; 52.24,26.99 52.48,27.24 52.48,29 52.93,29.45 52.93,30.22 53.67,30.96 v1(55.04,30.96)
  BOTTOM w0.508: C171.1 49.25,32.48 C170.1 46.21,32.48 v1(44.6,34.09) ; v1(65.27,38.8) 64.52,39.55 64.52,40.52 60.72,44.33 57.6,44.33 57.09,44.84 47.22,44.84 43.92,41.53 v1(43.92,40.58) ; v1(42.18,39.62) 42.18,34.63 v1(43.67,33.14) 49.89,26.93 52.18,26.93 52.24,26.99 52.24,25.68 55.47,22.44 59.31,22.44 60.06,23.2 62.62,23.2 67.9,17.91 67.9,16.12 70.16,13.86 73.03,13.86 v1(77.39,9.51)
  vias: v1(38.47,39.7)
SOC_BT_RST_N/PIR_IOT: length 5.5
  TOP w0.102: J14.16 95.18,48.17 92.08,48.17 R230.2 91.65,47.66 R229.2
SOC_BT_RST_PC17: length 37.1
  TOP w0.102: R229.1 81.53,47.65 78.67,44.79 76.24,44.79 v1(75.91,45.11) ; v1(68.85,46.35) 67.41,44.9 67.41,43.28 62.51,38.39 61.05,38.39 60.71,38.05 60.22,38.05 U7.B3
  BOTTOM w0.102: v1(75.91,45.11) 74.62,46.4 68.91,46.4 v1(68.85,46.35)
SOC_PWR_EN_IOT: length 89.3
  TOP w0.102: v1(67.02,61.25) v1(67.02,83.03)
  BOTTOM w0.102: J9.17 69.68,52.65 69.68,58.6 v1(67.02,61.25) ; D12.1 27.83,71.73 40.3,84.2 65.22,84.2 66.38,83.03 v1(67.02,83.03)
SOC_WIFI_OOB_PC15: length 45.2
  TOP w0.102: J14.1 92.73,59.44 83.08,59.44 71.9,48.26 71.47,48.26 67.82,44.6 67.82,43.08 62.78,38.05 61.35,38.05 61.05,37.75 U7.B4
SPEAK_EN: length 109
  TOP w0.102: v1(76.52,46.96) 72.96,43.4 72.96,42.49 68.76,38.29 68.76,37.47 65.57,34.28 61.04,34.28 60.72,33.96 59.98,33.96 U7.B10 ; v1(41.24,47.83) 31.89,47.83 27.72,52 27.72,53.68 9.97,71.43 9.97,76.92 R58.1 9.49,77.49 U10.1
  BOTTOM w0.102: v1(76.52,46.96) 76.25,47.23 64.47,47.23 63.43,48.27 41.68,48.27 v1(41.24,47.83)
TEST_TE: length 1.8
  TOP w0.102: U7.L13 v1(53.7,31.57)
  BOTTOM w0.102: v1(53.7,31.57) 53.1,31.57 TP16.1
TRST_: length 4.1
  TOP w0.102: v1(57.57,30.99) 58.31,30.99 U7.D14
  BOTTOM w0.102: v1(57.57,30.99) 57.57,28.37 TP15.1
TX+: length 22.8
  TOP w0.254: J13.1 6.99,15.16 6.32,15.16 5.28,16.2 5.28,21.22 7.52,23.46 11.52,23.46 13.2,21.77 16.71,21.77 17.66,22.73 U20.9
TX-: length 22.9
  TOP w0.254: U20.11 17.74,20.19 16.68,21.24 15.17,21.24 14.87,20.94 14.15,20.94 13.86,21.24 12.98,21.24 11.3,22.92 7.74,22.92 5.81,20.99 5.81,16.42 6.54,15.69 9.22,15.69 J13.2
TX_N0: length 6.8
  TOP w0.104: U20.6 27.94,20.19 29.06,21.31 29.54,21.31 29.98,20.87 30.35,20.5 30.35,19.68 30.86,19.17 31.69,19.17 31.81,19.05 U19.4
TX_P0: length 6.8
  TOP w0.104: U20.8 27.9,22.73 29.06,21.57 29.65,21.57 30.61,20.61 30.61,19.79 30.97,19.43 31.69,19.43 31.81,19.55 U19.3
UART1_RXD: length 34.2
  TOP w0.102: U7.F16 57.4,29.83 57.4,27.25 60.42,24.22 60.42,21.38 60.89,20.91 66.75,20.91 74.82,12.84 77.28,12.84 78.43,11.69 R42.1 78.42,10.21 R48.2
UART1_TXD: length 35.3
  TOP w0.102: U7.F15 57.62,30.25 57.62,27.34 60.65,24.32 60.65,21.48 60.99,21.13 66.87,21.13 74.85,13.15 77.29,13.15 78.98,11.47 78.98,10.54 R45.1 79.31,10.21 R51.2
UART2_RXD_PC14: length 39.4
  TOP w0.102: R215.1 89.04,51.64 v1(89.02,51.62) ; v1(89.02,50.48) 88.65,50.85 79.66,50.85 64.08,35.27 60.31,35.27 60.09,35.49 59.54,35.49 U7.C7
  BOTTOM w0.102: v1(89.02,50.48) v1(89.02,51.62)
UART2_TXD_PC13: length 42.9
  TOP w0.102: U7.B7 60.1,35.8 60.4,35.5 63.93,35.5 79.52,51.09 92.15,51.09 92.57,50.67 95.14,50.67 J14.12
USB_AVD08: length 3.4
  TOP w0.254: U7.R4 v1(51.1,38.07)
  BOTTOM w0.381: v1(51.1,38.07) 50.33,38.07 C136.1 C135.1 50.06,36.87 FB4.2
USB_AVD18: length 4.8
  TOP w0.254: U7.T3 v1(50.45,38.72)
  BOTTOM w0.381: FB5.2 46.32,38.19 C137.1 47.16,38.19 C138.1 48.25,38.19 48.78,38.72 v1(50.45,38.72)
USB_AVD33: length 5.6
  TOP w0.254: U7.R3 v1(51.1,38.72)
  BOTTOM w0.305: v1(51.1,38.72) 50.47,39.36 50.14,39.36
  BOTTOM w0.381: FB6.2 47.14,39.07 C139.1 C140.1 48.35,39.36 50.14,39.36
USB_DET_IOT: length 3.2
  TOP w0.102: R188.1 89.16,55.19 C9.1 88.27,55.19 R12.2 R10.1
USB_DM0: length 48.9
  TOP w0.13: U7.U1 50.1,39.68 49.32,39.68 41.81,47.19 8.17,47.19 D2.2 7.15,47.18 5.52,47.18 5.35,47.35 J2.2
USB_DP0: length 49.7
  TOP w0.13: U7.T2 50.45,39.37 49.2,39.37 41.69,46.88 8.17,46.88 D1.2 7.16,46.87 5.53,46.87 5.36,46.7 J2.3
USB_ID: length 2.6
  TOP w0.102: R55.1 48.22,39.05 U7.U2
USB_VBUS: length 5.3
  TOP w0.254: U7.U3 46.13,38.4 R24.1 45.85,39.57 R27.1
VCM: length 2.8
  TOP w0.254: U7.R2 v1(51.1,39.37)
  BOTTOM w0.305: v1(51.1,39.37) 51.06,39.37 50.18,40.26 C68.1 C69.1
VOUT: length 8
  BOTTOM w0.254: U16.2 73.1,71.87 R259.2 74.72,71.14 C198.1 75.59,71.14 R255.1
WIFI_MSC1_CLK_PC02: length 25
  TOP w0.102: U7.A1 60.7,39.87 62.39,39.87 65.85,43.34 65.85,53.7 67.42,55.27 72.18,55.27 J9.10
WIFI_MSC1_CMD_PC03: length 26.7
  TOP w0.102: J9.7 69.72,57.15 R246.2 68.51,55.94 67.46,55.94 65.41,53.88 65.41,43.25 62.26,40.1 60.44,40.1 60.19,39.86 60.19,39.58 59.97,39.36 59.75,39.36 59.57,39.18 59.57,38.74 U7.C3
WIFI_MSC1_D0_PC04: length 23.9
  TOP w0.102: J9.11 69.08,54.61 R247.2 68.61,54.19 67.18,54.19 66.27,53.29 66.27,43.37 62.51,39.61 60.88,39.61 60.65,39.37 60.36,39.37 60.04,39.05 U7.B2
WIFI_MSC1_D1_PC05: length 24
  TOP w0.102: U7.A2 60.66,39.05 60.99,39.38 62.64,39.38 66.56,43.3 66.56,52.35 67.51,53.3 68.61,53.3 R248.2 69.29,53.98 72.16,53.98 J9.14
WIFI_MSC1_D2_PC06: length 27.6
  TOP w0.102: J9.5 71.49,58.45 R249.2 68.59,57.99 67.34,57.99 66.67,57.32 66.67,56.18 64.76,54.27 64.76,43.38 61.96,40.58 60.32,40.58 59.53,39.8 59.53,39.54 59.22,39.24 U7.C2
WIFI_MSC1_D3_PC07: length 27.5
  TOP w0.102: U7.B1 59.88,39.84 60.37,40.33 62.17,40.33 65.12,43.29 65.12,54.1 66.98,55.95 66.98,56.63 67.26,56.91 68.51,56.91 R250.2 69.39,57.79 72.16,57.79 J9.6
WIFI_VBAT:
  vias: v1(84.24,61.95) v1(84.19,61.15) v1(85.44,61.95) v1(85.45,61.14)
WKUP: length 8.3
  TOP w0.102: TP13.1 54.5,21.72 54.5,26.74 55.33,27.56 U7.J17
N6876073: length 6.1
  TOP w0.305: 10.79,82.49 U10.6
  TOP w0.508: 10.79,82.49 11.36,81.92 C77.1 13.93,81.92 R56.1 R57.1
N6876131: length 1.7
  TOP w0.305: U10.4 11.44,77.62 R60.1
N6876183: length 0.7
  TOP w0.305: R60.2 C76.1
N6876193: length 0.7
  TOP w0.305: R59.2 C75.1
N7727802: length 1.2
  TOP w0.102: R95.2 72.79,38.77 D11.3
N7727853: length 1.2
  TOP w0.102: D11.2 69.86,37.97 R94.2
N16597671: length 1.7
  TOP w0.305: U10.3 10.79,77.64 R59.1
N16605475: length 1.5
  BOTTOM w0.102: R6.2 14.37,40.18 U1.11
N16605479: length 1.6
  BOTTOM w0.102: R7.2 13.87,40.57 U1.12
N16605539: length 1.4
  BOTTOM w0.246: U1.3 14.87,45.14 14.97,45.25 ; U1.4 15.37,45.19
N16605973: length 2.8
  BOTTOM w0.102: U1.13 12.94,42.34 11.97,41.37 R5.1 R4.1
N16626294: length 1.7
  BOTTOM w0.102: U2.4 97.06,44.48 R15.1
N16626314: length 0.7
  BOTTOM w0.203: R15.2 98.73,44.38
N16626426: length 2
  BOTTOM w0.203: U2.3 94.24,44.48 R17.2 93.11,44.49 R16.1
N16626534: length 7.8
  BOTTOM w0.203: 71.57,33.21 71.57,33.87 71.85,34.15 C34.1 R33.2
N16626558: length 3.7
  BOTTOM w0.203: C34.2 R33.1 R36.2 79.64,32.15 U5.1
N16626586: length 3.6
  BOTTOM w0.203: U3.1 25.92,49.4 R28.2 26.64,49.08 R25.1 27.67,49.08 C24.2
N16627048: length 3.2
  BOTTOM w0.203: U5.5 78.07,31.24 78.38,30.92 78.38,29.43 C206.1 78.27,29.29 R32.2
N16627350: length 3.3
  BOTTOM w0.203: R22.2 C96.1 26.71,51.35 27.07,50.98 U3.5
N16676856: length 3.8
  BOTTOM w0.203: C25.2 26.98,42.51 R23.1 26.98,42.51 R29.2 26.36,43 U4.1
N16677062: length 3.1
  BOTTOM w0.203: R26.2 26.52,46.27 C205.1 27.18,46.13 27.18,44.72 27.5,44.39 U4.5
N16732442: length 3.7
  TOP w0.102: R43.2 47.97,36.79 51.09,36.79 U7.R6
N16973565: length 1.7
  TOP w0.102: U7.F13 57.28,31.9 v1(57.6,31.58)
  BOTTOM w0.102: v1(57.6,31.58) 57.06,31.04 R116.2
N16973568: length 2.4
  TOP w0.102: U7.D9 58.9,34.18 v1(59.55,34.18)
  BOTTOM w0.102: v1(59.55,34.18) 60.71,34.18 R117.2
N16979467: length 3.2
  TOP w0.102: J4.4 79.39,7.24 D4.2 79.42,8.19 R51.1
N16979485: length 3.2
  TOP w0.102: R48.1 78.33,8.22 D5.2 78.39,7.22 J4.3
N16981740: length 5.4
  TOP w0.102: 50.97,41.44 51.93,40.47 51.93,39.62 52.38,39.17 52.38,38.74 U7.N3
  TOP w0.152: 50.97,41.44 50.75,41.66 50.75,42.12 50.43,42.44 C64.1
N16981743: length 5.4
  TOP w0.102: 50.4,41.51 50.11,41.23 50.11,41.06 50.31,40.86 50.53,40.86 50.7,41.03 50.89,41.03 50.99,40.93 50.99,40.59 51.1,40.49 51.53,40.49 51.73,40.29 51.73,39.54 52.08,39.19 U7.P2
  TOP w0.152: C65.1 50.18,42.19 50.4,41.97 50.4,41.51
N16981952: length 1.3
  TOP w0.254: U7.D4 v1(58.9,38.07)
  BOTTOM w0.254: v1(58.9,38.07) 59.51,38.68 R120.2
N16985653: length 4
  TOP w0.102: U7.E1 58.07,39.84 58.07,42.99 R38.2
N16990829: length 1.8
  TOP w0.305: R81.1 22.07,81.41 C85.1 22.07,80.52 R83.1
N16990879: length 3.3
  TOP w0.305: R81.2 22.08,83.33 R80.1
  TOP w0.33: R81.2 v1(22.79,82.46)
  BOTTOM w0.102: 22.79,82.46 v1(22.79,82.46)
  BOTTOM w0.381: C79.2 22.79,82.46
N16990962: length 3.1
  TOP w0.305: v1(18.33,82.47) R67.1 19.01,82.47 R69.2
  BOTTOM w0.102: 18.33,82.46 v1(18.33,82.47)
  BOTTOM w0.381: C79.1 18.33,82.46
N16994187: length 4.8
  TOP w0.102: U13.3 76.61,20.39 75.43,20.39 73.91,18.87 R142.2
N16994244: length 1.9
  TOP w0.102: C100.1 76.06,21.45 75.55,21.45 U13.4
N16994305: length 1.7
  BOTTOM w0.102: U12.4 71.49,14.8 C97.1
N16994361: length 1.6
  BOTTOM w0.102: U12.3 77.56,14.8 R141.2
N16994635: length 39.9
  TOP w0.102: R143.2 57.51,69.26 65.03,61.74 65.03,55.74 63.94,54.65 63.94,51.82 58.3,46.18 58.3,39.61 57.93,39.24 U7.E2
N17002165: length 1.8
  TOP w0.102: R191.2 36.01,22.87 U19.26
N17002179: length 2
  TOP w0.102: R195.2 33.01,15.68 U19.9
N17002181: length 1.9
  TOP w0.102: U19.10 33.51,15.65 32.95,15.1 R198.2
N17002261: length 2
  TOP w0.102: v1(34.01,22.36) U19.30
  BOTTOM w0.102: v1(34.01,22.36) 33.8,22.57 R209.1
N17002291: length 1.8
  TOP w0.102: R204.2 33.01,22.7 U19.32
N17002321: length 1.9
  TOP w0.102: U19.15 36.01,16.03 36.7,15.34 R190.2
N17002359: length 2.5
  TOP w0.254: U19.2 v1(31.56,20.05)
  BOTTOM w0.254: C118.1 31.56,19.96 v1(31.56,20.05) 31.74,20.24 C119.1
N17002395: length 2.6
  TOP w0.254: U19.29 v1(34.51,22.06)
  BOTTOM w0.381: C149.1 35.95,21.56 C150.1 35,21.56 v1(34.51,22.06)
N17002469: length 1.7
  TOP w0.102: U19.28 35.01,22.98 R201.2
N17002544: length 2.8
  TOP w0.102: U19.1 32.09,20.55 31.68,20.96 R194.1
N17002574: length 1.9
  TOP w0.381: U20.7 v1(26.18,21.46)
  BOTTOM w0.381: C156.2 v1(26.19,21.46)
N17002598: length 1.9
  TOP w0.381: U20.5 v1(26.18,18.92)
  BOTTOM w0.381: C155.2 v1(26.19,18.92)
N17002608: length 1.9
  TOP w0.381: U20.2 v1(26.18,15.11)
  BOTTOM w0.381: C154.2 26.19,15.1 v1(26.18,15.11)
N17002683: length 6.3
  TOP w0.102: R211.1 15.2,26.28 J13.11
N17002690: length 7.3
  TOP w0.102: R217.1 12.94,9.36 12.94,12.58 J13.13
N17006161: length 10.6
  TOP w0.254: R250.1 v1(67.43,57.45) ; R246.1 v1(67.43,56.48) ; R248.1 v1(67.44,53.75) ; R249.1 v1(67.43,58.45) ; R247.1 v1(67.44,54.64)
  TOP w0.381: v1(67.38,52.35) 67.39,52.34 R139.1 68.94,52.34 R98.1
  BOTTOM w0.305: v1(67.43,58.45) v1(67.43,57.45) v1(67.43,56.48) 67.43,54.64 v1(67.44,54.64) v1(67.44,53.75) 67.44,52.41 v1(67.38,52.35)
N17009042: length 2.9
  TOP w0.381: R92.2 82.23,88.38 Q4.2
N17009044: length 2.3
  TOP w0.102: Q5.3 75.13,88.39 R115.2 76.41,88.4 R113.2
N17009046: length 1.4
  TOP w0.102: R114.1 70.97,89.3 Q5.1
N17009287: length 1.6
  BOTTOM w0.102: Q6.3 95.2,64.11 R268.2
N17009319: length 1.6
  BOTTOM w0.102: R269.2 95.25,67.59 Q7.3
N17009402: length 13.4
  TOP w0.305: v1(82.82,69.85) 80.99,69.85 v1(80.98,69.84)
  BOTTOM w0.305: v1(80.98,69.84) U24.10 76.4,69.84 C201.1 75.82,68.3 R262.2 75.81,67.36 R258.1 ; R261.1 v1(82.82,69.85)
N17009422: length 11.7
  BOTTOM w0.305: R261.2 85.02,74.05 86.69,75.72 89.19,75.72 90.08,74.83 90.08,72.64 89.21,71.77 R253.1 88.65,71.76 R263.2
N17009484: length 3
  BOTTOM w0.305: U24.12 77.55,71.14 C199.1 76.65,71.11 R255.2
N17009506: length 6
  BOTTOM w0.305: C200.1 R260.1 76.45,72.33 R264.2 76.65,72.15 C199.2 77.88,71.79 U24.13
N17009512: length 4.3
  BOTTOM w0.305: C200.2 R260.2 77.51,74.04 C197.1 78.33,73.04 78.93,72.44 U24.14
N17009562: length 0.7
  BOTTOM w0.305: C202.1 R264.1
N17009566: length 1.1
  BOTTOM w0.305: R256.2 80.46,74.04 C197.2
N17009576: length 9.3
  BOTTOM w0.305: R256.1 81.51,69.56 81.14,69.19 U24.9 77.86,69.19 R254.1 77.73,69.32 C195.1
N17009610: length 14
  BOTTOM w0.305: U24.3 84.32,71.14 84.04,70.85 84.04,69.38 84.23,69.19 ; 84.23,69.19 U24.6 ; 84.23,69.19 84.03,69.19 83.22,68.38 ; 83.22,68.38 83.06,68.54 U24.8 77.99,68.54 R254.2 77.73,68.27 C195.2 ; 83.22,68.38 R257.1
N17009693: length 4.9
  BOTTOM w0.305: R266.2 88.65,68.01 C203.1 R263.1 88.64,69.84 U24.5
N17009695: length 3.8
  BOTTOM w0.305: U24.2 87.6,71.79 R253.2 87.62,72.65 C194.1 R227.1
N17058437: length 4
  TOP w0.102: U7.H15 56.28,30.3 56.28,26.97 R39.1
N17123098: length 2.2
  BOTTOM w0.254: R49.1 11.24,35.45 C36.1 12.09,35.57 U9.2
N17123136: length 1.2
  BOTTOM w0.102: R53.1 17.29,36.07 U9.6
N17123180: length 2.2
  BOTTOM w0.254: R50.1 11.24,36.19 C45.1 12.09,36.07 U9.3
N17123378: length 10.2
  TOP w0.102: U7.C11 59.54,32.88 60.04,32.88 60.25,32.68 67.5,32.68 R182.2 68.94,32.01 R181.2
N17123417: length 10.6
  TOP w0.102: U7.C10 59.53,33.55 60.12,33.55 60.31,33.73 60.84,33.73 61.09,33.98 65.62,33.98 66.64,35 67.47,35 R184.2 68.03,34.46 R183.2
N17141430: length 15.7
  TOP w0.102: v1(13.59,61.52) 11.87,61.52 9.76,63.63 J3.1
  BOTTOM w0.102: J3.1 8.28,68.67 Q2.3 ; Q1.1 15.42,62.19 C15.2 R21.2 v1(13.59,61.52)
N17141450: length 1.6
  BOTTOM w0.102: R231.2 14.04,70.78 D12.3
N17141452: length 2
  BOTTOM w0.246: 14.48,64.35 C15.1 R21.1
N17141508: length 2.6
  BOTTOM w0.102: Q2.1 12.07,71.53 R232.2 13.39,71.17 R231.1
N17141576: length 1.7
  TOP w0.102: 89.83,3.23 D13.1
  TOP w0.381: R234.2 89.83,3.23
N17211450: length 4.1
  TOP w0.102: C158.2 75.48,30.17 Y2.2 75.48,30.61 76.15,31.28 U21.1
N17211478: length 4.1
  TOP w0.102: U21.2 77.42,31.06 77.98,30.5 Y2.1 77.99,30.15 C159.2
N17217380: length 1.5
  BOTTOM w0.229: U23.10 95.51,23.63 C183.2
N17217382: length 1.5
  BOTTOM w0.229: C183.1 95.52,24.13 U23.11
N17217384: length 2.6
  BOTTOM w0.229: C182.1 94.81,24.89 95.79,24.89 96.05,24.63 U23.12
N17217386: length 2.6
  BOTTOM w0.229: U23.9 96,23.13 95.76,22.89 94.8,22.89 C182.2
N17217517: length 1.4
  BOTTOM w0.102: U23.1 100.47,24.63 R214.1
N17242896: length 6.9
  BOTTOM w0.203: R35.2 74.92,27.57 C35.1 69.04,27.57 68.83,27.36 TP9.1
N17242898: length 4.2
  BOTTOM w0.203: C35.2 74.92,26.53 R35.1 76.12,26.53 R37.2 76.13,25.45 75.74,25.07 U14.1
N17243021: length 3.3
  BOTTOM w0.102: U14.5 74.37,24.57 74.77,24.16 C108.1 75.6,22.45 R34.2
N17251040: length 1.6
  BOTTOM w0.203: R208.1 98.24,38.8 U6.4
N17251042: length 1.6
  BOTTOM w0.203: R173.2 99.76,38.32 R208.2
N17251086: length 2.3
  BOTTOM w0.203: U6.3 95.99,37.92 R91.1 95.99,39.17 R96.1
N170100671: length 1.4
  TOP w0.102: R226.2 71,87.4 Q5.2

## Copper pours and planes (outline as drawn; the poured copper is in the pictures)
1V8 on BOTTOM: 32.4,43.96 32.65,44.21 34.31,44.21 34.48,44.05 34.48,43.41 34.19,43.12 33.55,43.12 32.83,42.4 32.83,41.69 32.75,41.61 29.64,41.61 29.01,42.24 29.01,42.93 28.65,43.29 27.67,43.29 27.48,43.48 27.48,43.95 27.53,44.01 28.24,44.01 28.28,43.96
3V3 on TOP: 89.86,8.09 88.28,8.09 88.03,8.33 88.03,11.23 88.12,11.32 89.74,11.32 90.04,11.02 90.04,8.27
3V3 on TOP: 40.38,61.46 38.81,61.46 38.33,60.98 38.33,58.37 38.07,58.11 37.06,58.11 36.7,58.47 36.7,63.97 30.49,70.18 30.49,80.93 31.33,81.77 32.87,81.77 33.23,81.4 33.23,71.88 36.29,68.83 37.3,68.83 37.67,68.46 37.67,68.01 38.44,67.24 38.44,62.97 38.79,62.63 40.32,62.63 40.53,62.41 40.53,61.61
3V3 on TOP: 89.27,30 89.27,30.84 88.97,31.14 87.66,31.14 85.15,33.65 85.15,39.02 83,41.17 77.62,41.17 77.53,41.08 77.53,40.57 78.02,40.07 80.7,40.07 82.64,38.13 82.64,33.03 85.93,29.74 89.01,29.74
3V3 on TOP: 40.61,48.3 32.11,48.3 31.85,48.56 31.85,49.61 32.23,49.98 39.5,49.98 40.67,48.81 40.67,48.36
3V3 on BOTTOM: 29.44,82.17 32.87,82.17 33.25,81.79 33.25,80.76 32.82,80.33 31,80.33 30.5,79.83 29.71,79.83 29.23,80.31 29.23,81.96
3V3 on BOTTOM: outline of 93 points within 27.04,6.02 60.41,58.87
3V3 on BOTTOM: 40.25,48.28 56.37,48.28 57.56,49.47 62.63,49.47 64.69,47.42 75.79,47.42 76.79,46.42 76.79,39.27 75.44,37.92 68.01,37.92 67.83,37.74 67.83,37.28 68.1,37.01 77.08,37.01 78.33,38.26 78.33,40.2 78.34,40.21 78.34,47.8 77.31,48.83 66.24,48.83 63.54,51.53 57.67,51.53 55.62,49.47 40.38,49.47 39.93,49.02 39.93,48.6
3V3 on BOTTOM: 87.84,31.1 90.09,31.1 91.26,29.93 91.26,11.37 89.93,10.03 88.18,10.03 88.05,10.16 88.05,10.91 88.31,11.17 89.04,11.17 89.48,11.61 89.48,29.18 88.66,30 87.91,30 87.63,30.28 87.63,30.89
AVDD33 on BOTTOM: 32.79,15.57 32.48,15.57 32.26,15.79 32.26,16.57 30.57,18.26 30.57,21.44 31.98,22.86 32.37,22.86 32.44,22.78 32.44,22.35 31.03,20.93 31.03,18.6 31.53,18.09 32.29,18.09 32.49,18.3 32.83,18.3 32.95,18.18 32.95,15.72
GND on TOP: 2,0.51 0.95,0.95 0.51,2 0.51,89.95 0.95,91 2,91.44 100.82,91.44 101.88,91 102.31,89.95 102.31,2 101.88,0.95 100.82,0.51 ; 36 cut-outs
GND on BOTTOM: 2,0.51 0.95,0.95 0.51,2 0.51,89.95 0.95,91 2,91.44 100.82,91.44 101.88,91 102.31,89.95 102.31,2 101.88,0.95 100.82,0.51 ; 42 cut-outs
GND on L2_GND, L3_PWR: 0.51,89.95 0.95,91 2,91.44 100.82,91.44 101.88,91 102.31,89.95 102.31,2 101.88,0.95 100.82,0.51 2,0.51 0.95,0.95 0.51,2
VBAT2 on BOTTOM: 13.28,44.5 7.19,44.5 1.63,38.94 1.63,36.72 1.85,36.5 4.36,36.5 4.71,36.85 4.71,38.09 8.83,42.21 12.29,42.21 12.8,42.72 13.47,42.72 13.5,42.75 13.5,42.93 13.47,42.96 11.99,42.96 11.68,43.26 11.68,43.51 11.88,43.71 13.46,43.71 13.48,43.73 13.48,44.31
VCC_3V3 on BOTTOM: 91.54,40.75 91.55,40.73 91.55,39.16 92.04,38.68 94.72,38.68 95.01,38.39 95.01,37.34 94.94,37.27 93.31,37.27 93.11,37.08 89.45,37.08 88.48,38.04 88.48,38.6 88.79,38.91 88.79,40.84 88.79,44.01 88.23,44.58 88.23,45.54 88.26,45.57 88.26,47.31 88.42,47.47 89.97,47.47 91.54,45.91
VCC_5V on TOP: 6.64,47.85 7.34,48.56 11.03,48.56 11.38,48.91 11.38,51.08 10.94,51.52 9.12,51.52 8.22,50.62 7.3,50.62 6.86,50.18 4.05,50.18 3.77,49.9 3.77,48.02 3.94,47.85
VCC_5V on BOTTOM: 12.75,45.96 12.75,47.93 12.07,48.61 9.12,48.61 8.05,49.68 8.05,51.33 8.39,51.67 13.1,51.67 14.12,50.65 14.12,46.25 14.57,45.81 14.57,45.04 14.49,44.96 14.49,44.22 14.46,44.19 14.27,44.19 14.22,44.24 14.22,45.1 13.8,45.53 13.18,45.53
VCC_IN on BOTTOM: 15.1,48.62 17.25,48.62 17.35,48.53 19.45,48.53 19.75,48.82 19.75,58.87 18.33,60.29 13.12,60.29 12.72,59.89 12.72,54.65 14.84,52.52 14.84,48.88
VCC_IN on L3_PWR: 12.06,41.92 15.23,41.92 16.66,43.35 16.66,43.85 16.84,44.03 17.34,44.03 19.24,45.94 19.24,50.89 19.03,51.11 16.16,51.11 11.11,46.06 11.11,42.31 11.29,42.12 11.86,42.12
VCC_SOC on TOP: 41.53,61.46 43.03,61.46 43.14,61.57 43.14,62.81 42.98,62.97 41.58,62.97 41.39,62.79 41.39,61.59
VCC_SOC on BOTTOM: outline of 87 points within 18.26,21.8 87.1,76.91
